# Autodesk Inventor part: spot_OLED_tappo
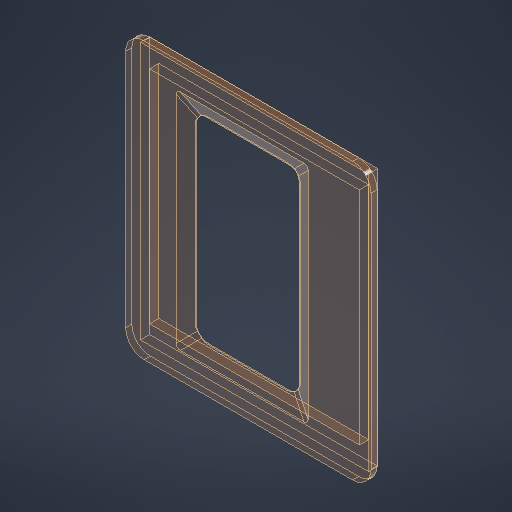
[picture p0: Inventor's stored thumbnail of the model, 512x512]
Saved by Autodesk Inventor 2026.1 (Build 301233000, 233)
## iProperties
Created: 2025-11
Part Number: spot_OLED_tappo
Material: Generico
Document SubType Name: Modeling
Designer: Gek
Density: 1 g/cm^3
Appearance: Policarbonato - Fumé
Author: Gek
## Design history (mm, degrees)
sketch "Schizzo1"
  geometry: L1 (20, 22.5)-(-20, 22.5); L2 (-20, 22.5)-(-20, -22.5); L3 (-20, -22.5)-(20, -22.5); L4 (20, -22.5)-(20, 22.5); L5 (20, 22.5)-(-20, -22.5); L6 (-20, 22.5)-(20, -22.5); 1 further point
  constraints: 12 end point, 2 midpoint, 2 parallel, 1 horizontal, 1 perpendicular
  dimensions: "d0" = 45 distance of L3.end L1.start; "d1" = 40 distance of L2.end L3.end
extrude "Estrusione1" new body sketch "Schizzo1" distance "d2" = 1; taper "d3" = 0 deg
sketch "Schizzo2"
  geometry: L1 (-18.6, -21.01)-(18.6, -21.01); L2 (18.6, -21.01)-(18.6, 21.01); L3 (18.6, 21.01)-(-18.6, 21.01); L4 (-18.6, 21.01)-(-18.6, -21.01); L5 (-18.6, -21.01)-(18.6, 21.01); L6 (18.6, -21.01)-(-18.6, 21.01); 1 further point
  constraints: 12 end point, 2 midpoint, 2 parallel, 1 horizontal, 1 perpendicular
  dimensions: "d4" = 37.2 distance of L1.start L1.end; "d5" = 42.02 distance of L3.end L1.start
extrude "Estrusione2" join sketch "Schizzo2" distance "d6" = 1.5; taper "d7" = 0 deg
sketch "Schizzo3"
  geometry: L1 (-17.1, -18)-(17.1, -18); L2 (17.1, -18)-(17.1, 18); L3 (17.1, 18)-(-17.1, 18); L4 (-17.1, 18)-(-17.1, -18); L5 (-17.1, -18)-(17.1, 18); L6 (17.1, -18)-(-17.1, 18); L7 (-18.6, 21.01)-(-18.6, -21.01) reference; L8 (-18.6, -21.01)-(18.6, -21.01) reference; 1 further point
  constraints: 12 end point, 2 midpoint, 2 parallel, 1 horizontal, 1 perpendicular
  dimensions: "d12" = 34.2 distance between parallel lines of L4 L2; "d13" = 36 distance between parallel lines of L3 L1
extrude "Estrusione3" cut sketch "Schizzo3" stored distance "d10" = 2; taper "d11" = 0 deg
sketch "Schizzo4"
  geometry: L1 (7.5, -16)-(-9.5, -16); L2 (-9.5, -16)-(-9.5, 16); L3 (-9.5, 16)-(7.5, 16); L4 (7.5, 16)-(7.5, -16); L5 (17.1, -18)-(17.1, 18) reference; L6 (-17.1, 18)-(-17.1, -18) reference; L7 (-28, 0)-(28, 0) reference; 1 further point
  constraints: 8 end point, 2 parallel, 1 horizontal, 1 perpendicular, 1 other
  dimensions: "d14" = 17 distance of L1.start L1.end; "d15" = 32 distance of L1.end L2.end; "d16" = 9.6 distance between parallel lines of L5 L4; "d17" = 7.6 distance between parallel lines of L6 L2 (derived)
extrude "Estrusione4" cut sketch "Schizzo4" distance "d18" = 10; taper "d19" = 0 deg
chamfer "Smusso1" distance "d20" = 2.25; stored, may be unused: second distance "d21" = 2, angle "d22" = 20 deg
fillet "Raccordo1" dims "d23" = 2
fillet "Raccordo2" dims "d24" = 3
node "Solido1"
